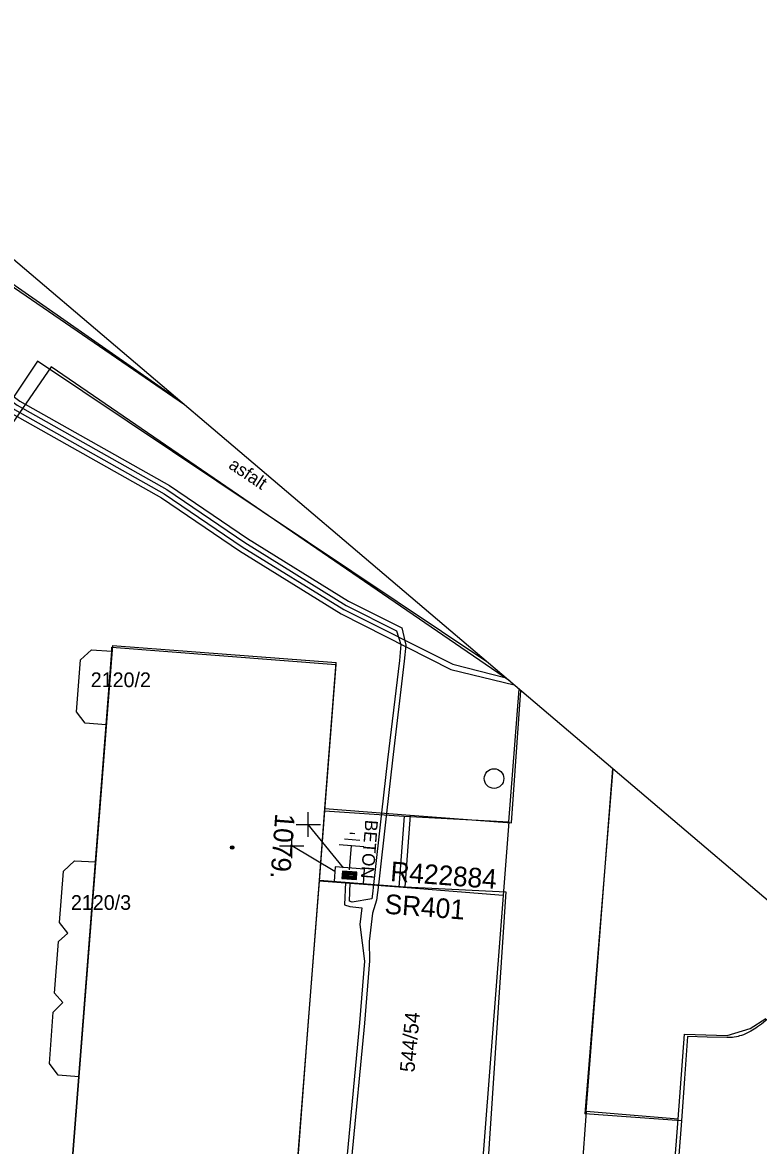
# Model space of a CAD drawing. Extents: x -540150 to -533593, y -1185082 to -1180066.
# Drawn here: x -536254.6 to -536217.1, y -1184369.3 to -1184312.1 of the extents above; entities that cross this region are included whole.
import ezdxf

# ---------------------------------------------------------------- set-up
doc = ezdxf.new("R2010")
doc.units = 0
for name, color, linetype in [('KN_HRAN_PARCEL', 7, 'Continuous'), ('KN_PARC_Č', 7, 'Continuous'), ('KN_VKP_HRAN_', 7, 'Continuous'), ('rámeček', 7, 'Continuous'), ('Vrstva 1', 7, 'Continuous'), ('Vrstva 10', 7, 'Continuous'), ('Vrstva 11', 7, 'Continuous'), ('Vrstva 14', 7, 'Continuous'), ('Vrstva 15', 7, 'Continuous'), ('Vrstva 27', 7, 'Continuous'), ('Vrstva 28', 7, 'Continuous'), ('Vrstva 29', 7, 'Continuous'), ('Vrstva 30', 7, 'Continuous'), ('Vrstva 34', 7, 'Continuous'), ('Vrstva 39', 7, 'Continuous'), ('Vrstva 40', 7, 'Continuous'), ('Vrstva 47', 7, 'Continuous'), ('Vrstva 5', 7, 'Continuous'), ('Vrstva 59', 7, 'Continuous'), ('Vrstva 8', 7, 'Continuous')]:
    doc.layers.add(name, color=color, linetype=linetype)

# ---------------------------------------------------------------- blocks, each defined once
blk = doc.blocks.new('NN800')
at = {"layer": 'Vrstva 1'}
for points in [[(-0.442, 0.442), (0.442, -0.442)], [(-0.442, -0.442), (0.442, 0.442)]]:
    blk.add_lwpolyline(points, dxfattribs=at)
blk = doc.blocks.new('NN620')
at = {"layer": 'Vrstva 8'}
for points in [[(0.752, 0.004), (-0.748, 0.004)], [(-0.748, 0.004), (-0.748, -0.746)], [(0.752, -0.746), (0.752, 0.004)], [(0.368, -0.18), (-0.376, -0.18)], [(-0.376, -0.18), (-0.376, -0.558)], [(-0.376, -0.558), (0.368, -0.558)], [(0.321, -0.227), (-0.329, -0.227)], [(-0.329, -0.227), (-0.329, -0.51)], [(-0.329, -0.51), (0.321, -0.51)], [(0.274, -0.274), (-0.281, -0.274)], [(-0.281, -0.274), (-0.281, -0.463)], [(-0.281, -0.463), (0.274, -0.463)], [(0.227, -0.321), (-0.234, -0.321)], [(-0.234, -0.321), (-0.234, -0.416)], [(-0.234, -0.416), (0.227, -0.416)], [(-0.193, -0.369), (0.185, -0.369)], [(0.227, -0.416), (0.227, -0.321)], [(0.274, -0.463), (0.274, -0.274)], [(0.321, -0.51), (0.321, -0.227)], [(0.368, -0.558), (0.368, -0.18)], [(-0.748, -0.746), (0.752, -0.746)]]:
    blk.add_lwpolyline(points, dxfattribs=at)
blk = doc.blocks.new('NN810')
at = {"layer": 'Vrstva 14'}
for points in [[(0.004, -0.64), (0.004, -1.89)], [(0.629, -1.89), (-0.621, -1.89)], [(0.388, -2.2), (-0.399, -2.2)], [(0.004, -2.515), (-0.124, -2.515)], [(0.137, -2.515), (0.004, -2.515)]]:
    blk.add_lwpolyline(points, dxfattribs=at)

msp = doc.modelspace()

# ---------------------------------------------------------------- linework, layer by layer
at = {"layer": 'KN_HRAN_PARCEL'}
for p, q in [((-536274.161, -1184312.475), (-536246.385, -1184331.558)), ((-536253.181, -1184329.625), (-536276.411, -1184363.405)), ((-536229.806, -1184345.637), (-536253.181, -1184329.625)), ((-536251.691, -1184344.555), (-536251.121, -1184344.045)), ((-536251.121, -1184344.045), (-536250.091, -1184344.115)), ((-536250.381, -1184347.875), (-536250.091, -1184344.115)), ((-536250.091, -1184344.115), (-536250.081, -1184343.925)), ((-536250.081, -1184343.925), (-536238.671, -1184344.805)), ((-536251.891, -1184347.215), (-536251.691, -1184344.555)), ((-536238.671, -1184344.805), (-536239.241, -1184352.255)), ((-536229.841, -1184352.825), (-536229.317, -1184346.052)), ((-536251.441, -1184347.795), (-536251.891, -1184347.215)), ((-536250.381, -1184347.875), (-536251.441, -1184347.795)), ((-536250.921, -1184354.865), (-536250.381, -1184347.875)), ((-536225.911, -1184367.585), (-536224.541, -1184350.107)), ((-536239.241, -1184352.255), (-536235.181, -1184352.525)), ((-536235.181, -1184352.525), (-536229.841, -1184352.825)), ((-536229.841, -1184352.825), (-536230.131, -1184356.565)), ((-536252.541, -1184355.335), (-536251.991, -1184354.805)), ((-536251.991, -1184354.805), (-536250.921, -1184354.865)), ((-536251.481, -1184362.095), (-536250.921, -1184354.865)), ((-536252.761, -1184357.955), (-536252.541, -1184355.335)), ((-536239.521, -1184355.835), (-536240.071, -1184362.975)), ((-536235.461, -1184356.145), (-536239.521, -1184355.835)), ((-536230.131, -1184356.565), (-536235.461, -1184356.145)), ((-536230.131, -1184356.565), (-536231.231, -1184370.805)), ((-536252.321, -1184358.485), (-536252.761, -1184357.955)), ((-536252.811, -1184358.915), (-536252.321, -1184358.485)), ((-536253.011, -1184361.545), (-536252.811, -1184358.915)), ((-536252.591, -1184362.025), (-536253.011, -1184361.545)), ((-536253.071, -1184362.515), (-536252.591, -1184362.025)), ((-536251.771, -1184365.815), (-536251.481, -1184362.095)), ((-536253.271, -1184365.135), (-536253.071, -1184362.515)), ((-536240.071, -1184362.975), (-536240.621, -1184370.155)), ((-536217.551, -1184363.345), (-536216.751, -1184362.835)), ((-536221.221, -1184367.975), (-536220.891, -1184363.645)), ((-536220.891, -1184363.645), (-536218.721, -1184363.705)), ((-536218.721, -1184363.705), (-536217.551, -1184363.345)), ((-536252.821, -1184365.735), (-536253.271, -1184365.135)), ((-536251.771, -1184365.815), (-536252.821, -1184365.735)), ((-536252.311, -1184372.815), (-536251.771, -1184365.815)), ((-536221.221, -1184367.975), (-536225.911, -1184367.585)), ((-536221.771, -1184375.185), (-536221.221, -1184367.975))]:
    msp.add_line(p, q, dxfattribs=at)
at = {"layer": 'KN_VKP_HRAN_'}
for p, q in [((-536239.241, -1184352.255), (-536239.521, -1184355.835)), ((-536235.181, -1184352.525), (-536235.461, -1184356.145)), ((-536225.911, -1184367.585), (-536226.441, -1184374.875))]:
    msp.add_line(p, q, dxfattribs=at)
at = {"layer": 'rámeček'}
msp.add_lwpolyline([(-536863.363, -1184184.148), (-536677.591, -1183965.383), (-535884.856, -1184638.563), (-536070.628, -1184857.328)], close=True, dxfattribs=at)
at = {"layer": 'Vrstva 10'}
msp.add_line((-536274.221, -1184312.095), (-536246.666, -1184331.319), dxfattribs=at)
for points in [[(-536215.962, -1184362.169), (-536216.071, -1184362.285), (-536216.224, -1184362.441), (-536216.367, -1184362.585), (-536216.503, -1184362.715), (-536216.631, -1184362.834), (-536216.752, -1184362.941), (-536216.866, -1184363.038), (-536216.973, -1184363.125), (-536217.075, -1184363.203), (-536217.171, -1184363.273), (-536217.262, -1184363.336), (-536217.348, -1184363.392), (-536217.429, -1184363.442), (-536217.506, -1184363.486)], [(-536220.731, -1184363.755), (-536220.891, -1184365.905), (-536221.051, -1184368.055), (-536221.183, -1184369.803), (-536221.385, -1184372.424)], [(-536217.506, -1184363.486), (-536217.579, -1184363.525), (-536217.647, -1184363.56), (-536217.776, -1184363.621), (-536217.891, -1184363.667), (-536217.993, -1184363.703), (-536218.083, -1184363.731), (-536218.163, -1184363.752), (-536218.233, -1184363.769), (-536218.357, -1184363.791), (-536218.451, -1184363.804), (-536218.523, -1184363.81), (-536218.631, -1184363.815), (-536218.741, -1184363.815), (-536219.736, -1184363.785), (-536220.731, -1184363.755)]]:
    msp.add_lwpolyline(points, dxfattribs=at)
at = {"layer": 'Vrstva 11'}
for p, q in [((-536253.881, -1184329.335), (-536276.511, -1184363.275)), ((-536230.96, -1184344.657), (-536253.881, -1184329.335)), ((-536229.711, -1184352.865), (-536229.232, -1184346.124)), ((-536224.545, -1184350.104), (-536225.966, -1184367.707)), ((-536239.224, -1184352.139), (-536234.871, -1184352.475)), ((-536234.871, -1184352.475), (-536235.141, -1184356.135)), ((-536234.871, -1184352.475), (-536229.711, -1184352.865)), ((-536239.506, -1184355.799), (-536235.141, -1184356.135)), ((-536235.141, -1184356.135), (-536230.001, -1184356.385)), ((-536230.001, -1184356.385), (-536230.941, -1184370.505)), ((-536221.051, -1184368.055), (-536225.966, -1184367.707))]:
    msp.add_line(p, q, dxfattribs=at)
at = {"layer": 'Vrstva 27'}
msp.add_circle((-536230.601, -1184350.615), 0.5, dxfattribs=at)
at = {"layer": 'Vrstva 39'}
for radius in [0.09, 0.0398]:
    msp.add_circle((-536243.95, -1184354.126), radius, dxfattribs=at)
at = {"layer": 'Vrstva 5'}
for q in [(-536254.291, -1184398.135), (-536238.651, -1184344.705)]:
    msp.add_line((-536250.051, -1184343.825), q, dxfattribs=at)
for points in [[(-536272.915, -1184323.013), (-536271.731, -1184322.262), (-536269.999, -1184322.371), (-536268.078, -1184322.553), (-536264.899, -1184324.001), (-536262.448, -1184325.663), (-536254.779, -1184331.378), (-536247.153, -1184335.676), (-536243.167, -1184338.38), (-536238.012, -1184341.571), (-536235.304, -1184342.926), (-536235.097, -1184343.807), (-536235.177, -1184344.628), (-536235.777, -1184349.679), (-536236.084, -1184352.381), (-536236.497, -1184356.031), (-536236.588, -1184356.819), (-536236.79, -1184357.466), (-536236.962, -1184358.914), (-536236.955, -1184359.908), (-536237.206, -1184363.076), (-536237.86, -1184369.972)], [(-536272.749, -1184323.128), (-536271.671, -1184322.525), (-536270.023, -1184322.619), (-536268.144, -1184322.797), (-536265.003, -1184324.229), (-536262.594, -1184325.867), (-536254.914, -1184331.589), (-536247.285, -1184335.889), (-536243.303, -1184338.59), (-536238.138, -1184341.787), (-536235.576, -1184343.082), (-536235.345, -1184343.783), (-536235.425, -1184344.602), (-536236.025, -1184349.651), (-536236.332, -1184352.362), (-536236.747, -1184356.011), (-536236.8, -1184356.481), (-536236.83, -1184356.737), (-536237.838, -1184356.91), (-536237.971, -1184356.864), (-536237.927, -1184355.921)], [(-536273.923, -1184324.797), (-536273.015, -1184325.391), (-536272.943, -1184325.311), (-536271.83, -1184324.744), (-536263.146, -1184326.131), (-536255.183, -1184332.012), (-536247.549, -1184336.314), (-536243.575, -1184339.01), (-536238.39, -1184342.219), (-536232.804, -1184345.048), (-536229.572, -1184345.835)], [(-536273.758, -1184324.546), (-536272.957, -1184325.079), (-536272.658, -1184324.858), (-536271.872, -1184324.486), (-536263.031, -1184325.905), (-536255.048, -1184331.801), (-536247.417, -1184336.101), (-536243.439, -1184338.8), (-536238.264, -1184342.003), (-536232.701, -1184344.775), (-536229.981, -1184345.488)], [(-536242.839, -1184399.042), (-536242.268, -1184391.628), (-536241.987, -1184387.992), (-536240.884, -1184373.68), (-536240.582, -1184369.762), (-536239.506, -1184355.799), (-536239.224, -1184352.139), (-536238.651, -1184344.705)], [(-536238.176, -1184355.901), (-536238.231, -1184357.046), (-536237.959, -1184357.134), (-536237.341, -1184357.205), (-536237.441, -1184358.055), (-536237.207, -1184359.922), (-536237.456, -1184363.054), (-536238.11, -1184369.952), (-536238.386, -1184373.872), (-536238.433, -1184374.588), (-536239.088, -1184374.555), (-536239.458, -1184373.79)]]:
    msp.add_lwpolyline(points, dxfattribs=at)
at = {"layer": 'Vrstva 59'}
for points in [[(-536238.274, -1184355.155), (-536240.071, -1184352.949)], [(-536238.71, -1184355.346), (-536240.915, -1184354.039)]]:
    msp.add_lwpolyline(points, dxfattribs=at)

# ---------------------------------------------------------------- block references
at = {"layer": 'Vrstva 15', "rotation": 175.64315828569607}
msp.add_blockref('NN810', (-536238.008, -1184355.911), dxfattribs=at)
at = {"layer": 'Vrstva 28', "rotation": 175.65466110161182}
msp.add_blockref('NN620', (-536238.008, -1184355.911), dxfattribs=at)
at = {"layer": 'Vrstva 34', "rotation": 45}
for p in [(-536240.071, -1184352.95), (-536240.915, -1184354.039)]:
    msp.add_blockref('NN800', p, dxfattribs=at)

# ---------------------------------------------------------------- texts
at = {"layer": 'KN_PARC_Č'}
for s, p in [('2120/2', (-536251.161, -1184345.955)), ('2120/3', (-536252.171, -1184357.305))]:
    msp.add_text(s, height=0.75, dxfattribs=at).set_placement(p)
msp.add_text('544/54', height=0.75, rotation=84.6, dxfattribs=at).set_placement((-536234.661, -1184365.605))
at = {"layer": 'Vrstva 29'}
msp.add_text('R422884', height=1, rotation=355.655, dxfattribs=at).set_placement((-536235.912, -1184355.833))
at = {"layer": 'Vrstva 30'}
msp.add_text('SR401', height=1, rotation=355.655, dxfattribs=at).set_placement((-536236.205, -1184357.494))
at = {"layer": 'Vrstva 40'}
for s, rotation, p in [('asfalt', 326.2403, (-536244.183, -1184334.763)), ('BETON', 265.5927, (-536237.162, -1184352.702))]:
    msp.add_text(s, height=0.65, rotation=rotation, dxfattribs=at).set_placement(p)
at = {"layer": 'Vrstva 47'}
msp.add_text('1079.', height=1, rotation=265.5927, dxfattribs=at).set_placement((-536241.748, -1184352.361))

doc.saveas('drawing.dxf')
